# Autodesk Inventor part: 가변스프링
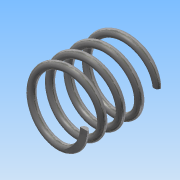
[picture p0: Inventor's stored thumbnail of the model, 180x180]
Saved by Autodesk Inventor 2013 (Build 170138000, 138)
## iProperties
Created: 2017-07
Part Number: 가변스프링
Material: 스테인리스강
Document SubType Name: Modeling
Designer: Administrator
Density: 8.08 g/cm^3
Mass: 5.30916 g
Surface Area: 13.3836 cm^2
Volume: 0.657075 cm^3
Author: Administrator
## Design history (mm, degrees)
sketch "스케치1"
  geometry: L1 (8.5, 0)-(0, 0); L2 (0, 0)-(0, 20.5); L3 (0, 20.5)-(8.5, 20.5); C1 r 1 at (8.5, 0)
  constraints: 6 end point, 1 centre point, 1 horizontal, 1 horizontal alignment, 1 parallel, 1 perpendicular
  dimensions: "d0" = 2 diameter of C1; "d1" = 8.5 distance of L1.start L1.end; "d2" = 8.5 distance of L2.end L3.end; "d3" = 20.5 distance of L1.end L2.end (derived)
feature "코일2" sketch "스케치1" pitch "d17" = 10; turns "d19" = 4; dims "d18" = 20.5 (= d3), "d20" = 0, angle "d21" = 90 deg, angle "d22" = 90 deg, "d23" = 0, "d24" = 0
sketch "스케치3"
  geometry: L1 (0, 15)-(20.5, 15); L2 (20.5, 15)-(20.5, -15); L3 (20.5, -15)-(0, -15); L4 (0, -15)-(0, 15); 2 further points
  constraints: 8 end point, 2 parallel, 1 coincident, 1 horizontal, 1 midpoint, 1 perpendicular
  dimensions: "d25" = 30 distance of L1.end L2.end; "d27" = 20.5 distance of L1.start L1.end (derived)
extrude "돌출2" sketch "스케치3" stored distance "d28" = 30; taper "d29" = 0 deg
node "솔리드2"
